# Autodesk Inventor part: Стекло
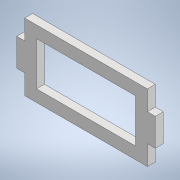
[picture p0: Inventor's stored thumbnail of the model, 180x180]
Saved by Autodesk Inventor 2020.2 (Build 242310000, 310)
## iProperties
Created: 2020-04
Part Number: Стекло
Material: Типовые
Document SubType Name: Modeling
Designer: Алексей
Density: 1 g/cm^3
Appearance: По умолчанию
Author: Алексей
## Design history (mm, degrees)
sketch "Эскиз1"
  geometry: L1 (60, 13.679)-(60, -0.321) reference; L2 (56, 13.679)-(60, 13.679) reference; L3 (56, -0.321)-(56, 13.679) reference; L4 (56, -0.321)-(60, -0.321) reference; L5 (-6, 13.679)-(-6, -0.321) reference; L6 (60, 23.665)-(56, 23.665) reference; L7 (-6, 23.665)-(-10, 23.665) reference; L8 (-6, -10.307)-(-10, -10.307) reference; L9 (60, -10.307)-(56, -10.307) reference; L10 (56, 23.665)-(-6, 23.665); L11 (-6, 23.665)-(-6, -10.307); L12 (-6, -10.307)-(56, -10.307); L13 (56, -10.307)-(56, 23.665); L14 (50, 17.665)-(0, 17.665); L15 (0, 17.665)-(0, -4.307); L16 (0, -4.307)-(50, -4.307); L17 (50, -4.307)-(50, 17.665); L18 (-6, 13.679)-(-10, 13.679); L19 (-10, 13.679)-(-10, -0.321); L20 (-10, -0.321)-(-6, -0.321); L21 (-6, -0.321)-(-6, 13.679); 3 further points
  constraints: 24 end point, 6 parallel, 3 horizontal, 3 perpendicular
  dimensions: "d0" = 6 distance between parallel lines of L10 L14; "d1" = 6 distance between parallel lines of L12 L16; "d2" = 6 distance between parallel lines of L3 L17; "d3" = 6 distance between parallel lines of L11 L15; "d6" = 4 distance of L20.end L19.end; "d7" = 14 distance of L19.end L18.end
extrude "Выдавливание1" new body sketch "Эскиз1" distance "d4" = 4; taper "d5" = 0 deg
node "Твердое тело1"
node "Ссылка1"
node "Ссылка3"
node "Ссылка4"
node "Ссылка5"
node "Ссылка6"
